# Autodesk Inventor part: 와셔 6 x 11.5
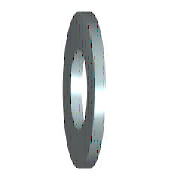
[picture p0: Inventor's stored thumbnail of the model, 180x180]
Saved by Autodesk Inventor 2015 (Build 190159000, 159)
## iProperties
IsCustomPart: 1
Created: 2012-02
Part Number: 와셔 6 x 11.5
Material: 강철, 연강
Description: 평면 와셔
Document SubType Name: Modeling
Standard: KS B 1326
Designer: mduedu
Standards Organization: KS
Language: ko-KR
Size Designation: 6x11.5
Categories: <MemberInstance><Categories><Category DisplayName="조임쇠" InternalName="e4da775c-781d-43d5-af7c-5136215cf5a6" Mnemonic="FSTN"><Category DisplayName="와셔" InternalN
Density: 7.86 g/cm^3
Mass: 0.901687 g
Surface Area: 2.33373 cm^2
Volume: 0.114718 cm^3
Appearance: 주황색
Author: mduedu
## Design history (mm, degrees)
sketch "스케치"
  geometry: C1 r 5.75 at (0, 0); C2 r 3.2 at (0, 0); 1 further point
  constraints: 2 centre point, 2 coincident
  dimensions: "d0" = 6.4 diameter of C2 (= SD1); "d1" = 11.5 diameter of C1 (= SD2)
extrude "본체" new body sketch "스케치" distance "d2" = 1.6 (= SD); taper "d3" = 0 deg
workaxis "Work Axis1"
workplane "Work Plane1"
body "Solid1"
other parameters: "SD1" = 6.4 [user parameter; used in 1 equation term], "SD2" = 11.5 [user parameter; used in 1 equation term], "SD" = 1.6 [user parameter; used in 1 equation term], "d4" = 0, "d5" = 0, "d6" = 0, "d7" = 0, "NND" = 6 [user parameter]
